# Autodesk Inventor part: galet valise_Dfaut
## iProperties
Created: 2007-07
Part Number: galet valise_Dfaut
Document SubType Name: Modeling
Designer: EF
Density: 1 g/cm^3
Author: EF
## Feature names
1. Base1
